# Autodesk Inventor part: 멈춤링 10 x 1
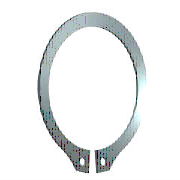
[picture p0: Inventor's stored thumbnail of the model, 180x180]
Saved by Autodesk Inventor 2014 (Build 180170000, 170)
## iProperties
IsCustomPart: 0
Created: 2009-02
Part Number: 멈춤링 10 x 1
Material: Steel, Mild
Description: 리테이닝 링(C형)
Document SubType Name: Modeling
Standard: KS B 1336
Designer: SeoGD™
Standards Organization: KS
Language: ko-KR
Size Designation: 10 x 1
Categories: <MemberInstance><Categories><Category DisplayName="샤프트 부품" InternalName="7f7aeb1f-a693-4053-b835-cee3144e0d98" Mnemonic="SHFT"><Category DisplayName="써클립" Inter
Density: 7.86 g/cm^3
Appearance: Metal-Steel
Mass: 0.423087 g
Surface Area: 1.9243 cm^2
Volume: 0.0538279 cm^3
Author: SeoGD™
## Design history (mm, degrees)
sketch "스케치1"
  geometry: L1 (-6, 0)-(6, 0) reference; L2 (0, 20.189)-(0, -80.536) reference; L3 (-48.09, 0)-(48.09, 0) reference; L4 (-0.3, -9.791)-(-0.3, -12.791); L5 (-0.3, -6.54)-(-0.3, -13.29); L6 (-2.795, 1.6)-(3.672, 1.6); L7 (0.3, -6.54)-(0.3, -13.29); L8 (0.3, -9.791)-(0.3, -12.791); C1 r 0.6 at (-1.2, -11.486); C2 r 0.6 at (1.2, -11.486); A1 r 4.8 centre (0, -5) between (0.3, -9.791) and (-0.3, -9.791); A2 r 6.2 centre (0, -4.6) between (2.988, -10.033) and (-2.988, -10.033); A3 r 7.796 centre (0, -5) between (-1.418, -12.666) and (-0.3, -12.791); A4 r 1.2 centre (-1.2, -11.486) between (-2.383, -11.285) and (-1.418, -12.666); A5 r 1.2 centre (-3.566, -11.084) between (-2.383, -11.285) and (-2.988, -10.033); A6 r 1.2 centre (3.566, -11.084) between (2.988, -10.033) and (2.383, -11.285); A7 r 1.2 centre (1.2, -11.486) between (1.418, -12.666) and (2.383, -11.285); A8 r 7.796 centre (0, -5) between (0.3, -12.791) and (1.418, -12.666)
  constraints: 16 point on circle, 12 end point, 10 centre point, 9 symmetric about line, 5 point on line, 4 tangent, 3 coincident, 2 horizontal, 1 perpendicular, 1 vertical, 5 other
  dimensions: "d0" = 9.6 diameter of A1 (= ND); "d1" = 3 distance of L4.end L4.start (= SRB2); "d6" = 0.3 distance between parallel lines of L2 L5 (= 0.25 x SD5); "d7" = 1.6 distance between parallel lines of L6 L3 (= SRB1); "d8" = 0.4 distance of A1.centre A2.centre (= 0.25 x SRB1); "d9" = 1.2 radius of A4 (= SD5); "d10" = 1.2 radius of A5 (= SD5); "d11" = 0.9 distance from line of L4 A4.centre (= 0.75 x SD5); "d12" = 1.2 diameter of C1 (= SD5); "d13" = 1.2 diameter of C2 (= SD5); "d14" = 5 distance from line of A1.centre L1 (= 0.5 x WD)
extrude "본체" new body sketch "스케치1" distance "d2" = 1 (= SD); taper "d3" = 0 deg
workaxis "Work Axis1"
workplane "Work Plane1"
body "Solid1"
other parameters: "SD" = 1 [user parameter; used in 1 equation term], "SRB1" = 1.6 [user parameter; used in 2 equation terms], "ND" = 9.6 [user parameter; used in 1 equation term], "SRB2" = 3 [user parameter; used in 1 equation term], "SD5" = 1.2 [user parameter; used in 6 equation terms], "d15" = 0, "d16" = 0, "d17" = 0, "d41" = 0, "d42" = 0, "SD3" = 9.3 [user parameter], "WDMAX" = 11 [user parameter]
